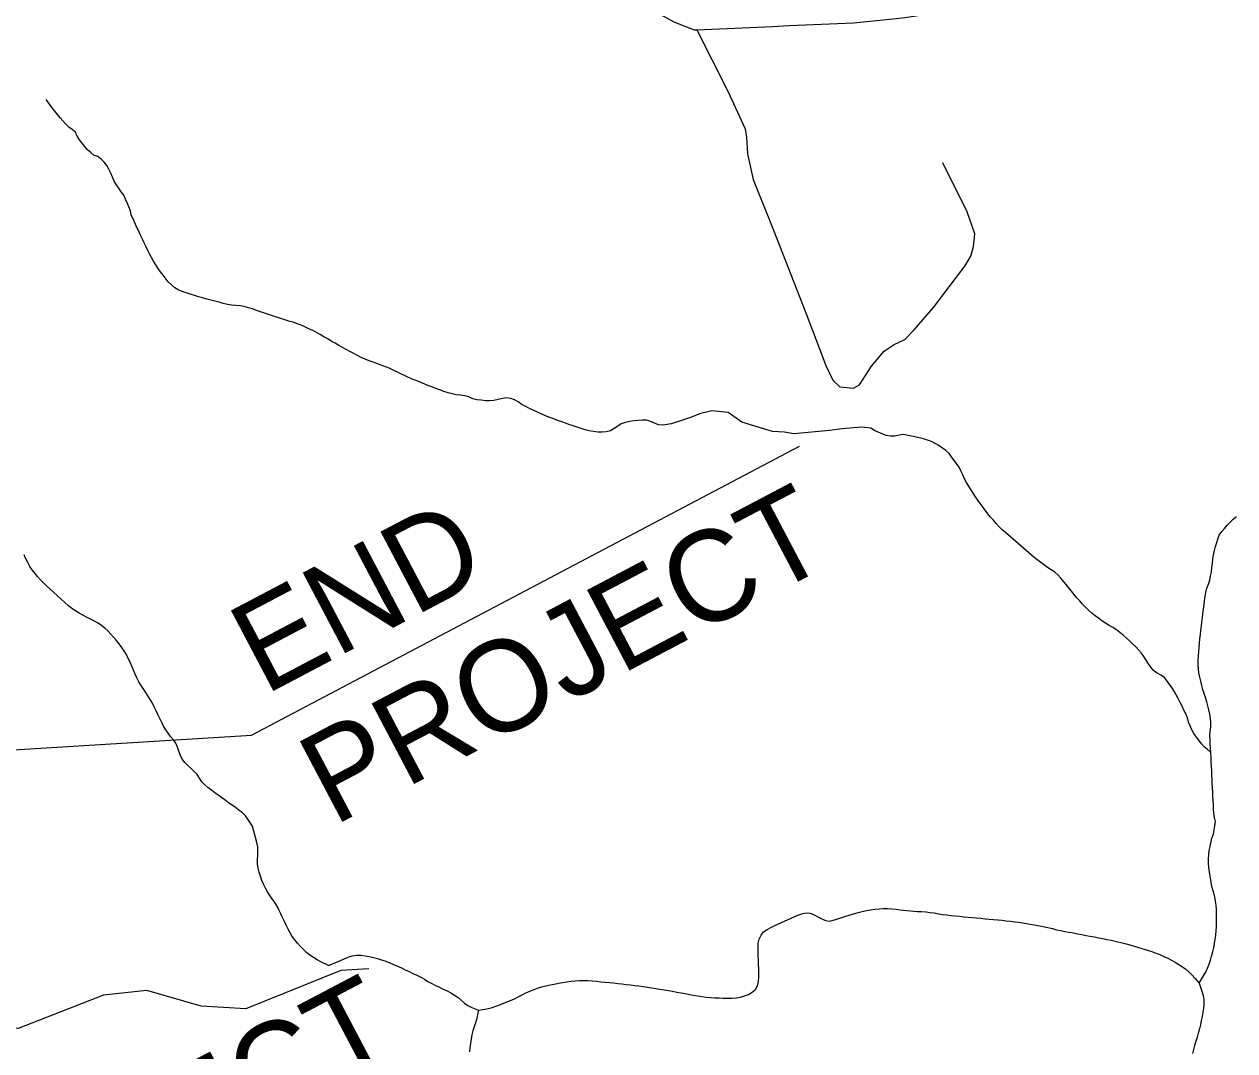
# Model space of a CAD drawing. Extents: x 1379448 to 1382868, y 593769 to 596827.
# Drawn here: x 1379976 to 1380162.2, y 595600.1 to 595758 of the extents above; entities that cross this region are included whole.
import ezdxf

# ---------------------------------------------------------------- set-up
doc = ezdxf.new("R2010")
doc.units = 0
for name, color, linetype in [('Old_Level_11', 7, 'Continuous'), ('Old_Level_32', 7, 'Continuous'), ('Old_Level_35', 7, 'Continuous'), ('Old_Level_59', 7, 'Continuous'), ('Old_Level_62', 7, 'Continuous')]:
    doc.layers.add(name, color=color, linetype=linetype)

msp = doc.modelspace()

# ---------------------------------------------------------------- linework, layer by layer
at = {"layer": 'Old_Level_11'}
for p, q in [((1380010.99, 595648.67), (1380095.29, 595693.12)), ((1379924.01, 595643.23), (1380010.99, 595648.67))]:
    msp.add_line(p, q, dxfattribs=at)
at = {"layer": 'Old_Level_32'}
msp.add_lwpolyline([(1380034.62, 595764.81), (1380038.89, 595766.64), (1380042.27, 595767.47), (1380047.28, 595767.89), (1380058.23, 595765.94), (1380063.55, 595764.52), (1380070.37, 595761.5), (1380075.96, 595758.38), (1380079.07, 595757.17), (1380079.47, 595757.16), (1380091.16, 595757.66), (1380093.69, 595757.86), (1380103.6, 595758.24), (1380110.14, 595758.91), (1380111.56, 595759.05), (1380126.48, 595761.37), (1380131.43, 595762.22), (1380136.18, 595763.33), (1380139.9, 595764.02), (1380148.64, 595765.89), (1380153.3, 595766.99)], dxfattribs=at)
at = {"layer": 'Old_Level_35'}
msp.add_lwpolyline([(1380079.47, 595757.16), (1380084.28, 595747.74), (1380086.91, 595741.93), (1380087.13, 595740.67), (1380087.29, 595738.11), (1380088.18, 595734.14), (1380091.29, 595726.37), (1380096.26, 595713.65), (1380099.33, 595705.54), (1380100.42, 595703.26), (1380101.51, 595702.24), (1380103.57, 595702.06), (1380104.5, 595702.55), (1380106.36, 595705.44), (1380108.31, 595707.74), (1380109.85, 595708.76), (1380111.51, 595709.53), (1380112.91, 595711.01), (1380115.88, 595714.47), (1380120.71, 595720.83), (1380121.63, 595722.37), (1380122.05, 595723.86), (1380122.25, 595725.77), (1380121.1, 595729.18), (1380117.34, 595736.72)], dxfattribs=at)
at = {"layer": 'Old_Level_59'}
for points in [[(1380029.06, 595612.69), (1380024.72, 595612.43), (1380010.13, 595606.57), (1380003.24, 595606.94), (1379994.91, 595609.37), (1379988.23, 595608.66), (1379975.1, 595603.54), (1379971.47, 595604.07), (1379963.32, 595610.7), (1379954.37, 595613.7), (1379940.34, 595615.62), (1379920.78, 595632.39), (1379911.66, 595641.62), (1379894.65, 595661.43), (1379873.48, 595677.68), (1379868.88, 595686.83), (1379868.53, 595690.48), (1379874.38, 595703.4), (1379871.94, 595708.2), (1379865.99, 595712.11)], [(1380156.77, 595610.51), (1380157.17, 595609.26), (1380157.36, 595608.63), (1380157.5, 595607.99), (1380157.5, 595607.33), (1380157.42, 595606.68), (1380157.33, 595606.03), (1380157.22, 595605.38), (1380157.09, 595604.74), (1380156.95, 595604.09), (1380156.8, 595603.46), (1380156.63, 595602.82), (1380156.44, 595602.19), (1380156.25, 595601.56), (1380156.07, 595600.93), (1380155.9, 595600.3), (1380155.75, 595599.66)]]:
    msp.add_lwpolyline(points, dxfattribs=at)
at = {"layer": 'Old_Level_62'}
for points in [[(1379985.36, 595739.22), (1379984.94, 595739.72), (1379984.54, 595740.25), (1379984.17, 595740.79), (1379983.91, 595741.4), (1379983.43, 595741.83), (1379982.87, 595742.2), (1379982.41, 595742.66), (1379981.97, 595743.15), (1379981.55, 595743.65), (1379981.13, 595744.16), (1379980.72, 595744.67), (1379980.32, 595745.19), (1379979.93, 595745.72), (1379979.42, 595746.45)], [(1380043.15, 595700.95), (1380042.49, 595701.02), (1380041.85, 595701.15), (1380041.22, 595701.33), (1380040.6, 595701.54), (1380039.98, 595701.76), (1380039.36, 595701.99), (1380038.75, 595702.22), (1380038.13, 595702.46), (1380037.53, 595702.7), (1380036.91, 595702.95), (1380036.31, 595703.2), (1380035.7, 595703.45), (1380033.94, 595704.27), (1380032.16, 595705.12), (1380029.7, 595706.03), (1380029.08, 595706.24), (1380028.48, 595706.5), (1380027.88, 595706.77), (1380027.29, 595707.07), (1380026.71, 595707.36), (1380026.13, 595707.67), (1380025.55, 595707.98), (1380024.98, 595708.31), (1380024.41, 595708.63), (1380023.84, 595708.96), (1380023.27, 595709.29), (1380022.71, 595709.62), (1380022.14, 595709.95), (1380021.57, 595710.28), (1380020.99, 595710.59), (1380020.41, 595710.9), (1380019.82, 595711.19), (1380019.22, 595711.46), (1380018.62, 595711.72), (1380018.01, 595711.96), (1380017.39, 595712.18), (1380016.76, 595712.35), (1380013.01, 595713.58), (1380012.4, 595713.8), (1380011.77, 595714.01), (1380011.15, 595714.22), (1380010.52, 595714.41), (1380009.89, 595714.58), (1380009.25, 595714.69), (1380008.59, 595714.75), (1380007.93, 595714.81), (1380007.29, 595714.93), (1380006.65, 595715.09), (1380006.01, 595715.25), (1380005.37, 595715.41), (1380004.73, 595715.57), (1380004.1, 595715.75), (1380003.46, 595715.92), (1380002.83, 595716.1), (1380002.2, 595716.29), (1380001.57, 595716.49), (1380000.95, 595716.69), (1380000.34, 595716.92), (1379999.73, 595717.15), (1379999.18, 595717.48), (1379998.67, 595717.92), (1379998.19, 595718.39), (1379997.42, 595719.41), (1379997.02, 595719.94), (1379996.64, 595720.47), (1379996.27, 595721.02), (1379995.92, 595721.57), (1379995.62, 595722.15), (1379995.31, 595722.73), (1379995.02, 595723.32), (1379994.73, 595723.91), (1379994.44, 595724.5), (1379994.16, 595725.09), (1379993.87, 595725.68), (1379993.6, 595726.28), (1379993.32, 595726.88), (1379993.05, 595727.47), (1379992.77, 595728.07), (1379992.5, 595728.66), (1379992.36, 595729.31), (1379992.13, 595729.92), (1379991.89, 595730.54), (1379991.63, 595731.14), (1379991.33, 595731.72), (1379990.97, 595732.27), (1379990.58, 595732.8), (1379990.21, 595733.34), (1379989.89, 595733.91), (1379989.61, 595734.51), (1379989.34, 595735.12), (1379989.06, 595735.71), (1379988.75, 595736.28), (1379988.35, 595736.8), (1379987.86, 595737.26), (1379987.35, 595737.67), (1379986.77, 595737.85), (1379986.27, 595738.28), (1379985.79, 595738.73), (1379985.36, 595739.22)], [(1380111.24, 595694.91), (1380110.6, 595694.8), (1380109.93, 595694.68), (1380109.27, 595694.65), (1380108.63, 595694.78), (1380108.02, 595695.02), (1380107.41, 595695.27), (1380106.82, 595695.55), (1380106.26, 595695.89), (1380104.85, 595696.06), (1380103.61, 595695.93), (1380101.86, 595695.79), (1380099.9, 595695.54), (1380094.42, 595695.01), (1380092.97, 595695.29), (1380091.11, 595695.35), (1380088.92, 595696.03), (1380086.42, 595696.81), (1380084.31, 595698.32), (1380081.82, 595698.57), (1380079.89, 595698.09), (1380079.29, 595697.83), (1380078.68, 595697.59), (1380078.06, 595697.37), (1380077.44, 595697.15), (1380076.82, 595696.94), (1380076.19, 595696.74), (1380075.56, 595696.57), (1380074.91, 595696.43), (1380074.25, 595696.36), (1380073.61, 595696.41), (1380072.99, 595696.64), (1380072.37, 595696.92), (1380071.75, 595697.1), (1380071.1, 595697.12), (1380070.44, 595697.09), (1380069.78, 595697.02), (1380069.12, 595696.91), (1380068.48, 595696.76), (1380067.88, 595696.54), (1380067.32, 595696.19), (1380066.77, 595695.82), (1380066.19, 595695.5), (1380065.56, 595695.3), (1380064.91, 595695.25), (1380064.25, 595695.29), (1380063.6, 595695.35), (1380062.95, 595695.47), (1380062.32, 595695.65), (1380061.7, 595695.85), (1380061.07, 595696.05), (1380060.45, 595696.26), (1380059.82, 595696.47), (1380059.21, 595696.69), (1380058.59, 595696.91), (1380057.97, 595697.13), (1380057.35, 595697.36), (1380056.74, 595697.6), (1380056.14, 595697.86), (1380053.77, 595698.9), (1380053.18, 595699.2), (1380052.6, 595699.55), (1380052.03, 595699.92), (1380051.46, 595700.23), (1380050.87, 595700.46), (1380050.24, 595700.53), (1380049.6, 595700.46), (1380048.94, 595700.3), (1380048.28, 595700.15), (1380047.62, 595700.08), (1380046.97, 595700.1), (1380046.31, 595700.17), (1380045.66, 595700.27), (1380045.02, 595700.4), (1380044.42, 595700.69), (1380043.8, 595700.88), (1380043.15, 595700.95)], [(1380158.55, 595646), (1380158.06, 595646.43), (1380157.56, 595646.86), (1380157.1, 595647.33), (1380155.96, 595648.9), (1380155.65, 595649.49), (1380155.37, 595650.08), (1380155.11, 595650.68), (1380154.96, 595651.32), (1380154.69, 595651.92), (1380154.41, 595652.51), (1380154.13, 595653.1), (1380153.83, 595653.69), (1380153.54, 595654.28), (1380153.23, 595654.86), (1380152.92, 595655.43), (1380152.55, 595655.98), (1380151.42, 595657.54), (1380150.87, 595657.89), (1380150.29, 595658.21), (1380149.76, 595658.6), (1380149.35, 595659.1), (1380148.98, 595659.65), (1380148.63, 595660.21), (1380148.27, 595660.77), (1380147.88, 595661.29), (1380147.45, 595661.79), (1380147, 595662.26), (1380146.53, 595662.72), (1380146.05, 595663.17), (1380145.56, 595663.61), (1380145.06, 595664.04), (1380144.55, 595664.45), (1380144.03, 595664.85), (1380143.5, 595665.24), (1380142.92, 595665.55), (1380142.35, 595665.87), (1380141.81, 595666.25), (1380141.28, 595666.64), (1380140.76, 595667.04), (1380140.25, 595667.45), (1380139.75, 595667.88), (1380139.27, 595668.33), (1380138.82, 595668.8), (1380138.39, 595669.3), (1380137.97, 595669.8), (1380137.56, 595670.32), (1380136.32, 595671.82), (1380135.47, 595672.82), (1380135.05, 595673.32), (1380134.55, 595673.74), (1380134.01, 595674.11), (1380133.45, 595674.47), (1380131.37, 595676), (1380126.95, 595679.82), (1380126.47, 595680.27), (1380126.01, 595680.73), (1380125.56, 595681.22), (1380125.12, 595681.71), (1380124.69, 595682.21), (1380124.28, 595682.71), (1380122.74, 595684.79), (1380122.38, 595685.33), (1380120.98, 595687.53), (1380120.69, 595688.11), (1380120.41, 595688.71), (1380120.12, 595689.31), (1380119.83, 595689.89), (1380118.69, 595691.48), (1380118.29, 595692), (1380117.81, 595692.43), (1380117.29, 595692.83), (1380116.73, 595693.21), (1380116.16, 595693.54), (1380115.58, 595693.82), (1380114.97, 595694.06), (1380114.34, 595694.25), (1380113.7, 595694.41), (1380113.05, 595694.56), (1380111.24, 595694.91)], [(1380158.55, 595646), (1380158.48, 595647.31), (1380158.44, 595647.96), (1380158.42, 595648.62), (1380158.46, 595649.27), (1380158.55, 595649.93), (1380158.57, 595650.58), (1380158.49, 595651.23), (1380158.39, 595651.88), (1380158.26, 595652.53), (1380158.12, 595653.17), (1380157.95, 595653.8), (1380157.76, 595654.43), (1380157.55, 595655.05), (1380157.35, 595655.68), (1380157.18, 595656.31), (1380157.01, 595656.95), (1380156.85, 595657.59), (1380156.73, 595658.23), (1380156.66, 595658.88), (1380156.62, 595659.54), (1380156.62, 595660.19), (1380156.64, 595660.85), (1380156.69, 595661.51), (1380156.75, 595662.16), (1380156.81, 595662.81), (1380156.88, 595663.47), (1380156.95, 595664.12), (1380157.02, 595664.78), (1380157.1, 595665.43), (1380157.18, 595666.08), (1380157.26, 595666.73), (1380157.34, 595667.38), (1380157.42, 595668.03), (1380157.52, 595668.69), (1380157.6, 595669.33), (1380157.7, 595669.98), (1380157.8, 595670.63), (1380157.96, 595671.27), (1380158.19, 595671.89), (1380158.4, 595672.51), (1380158.53, 595673.15), (1380158.64, 595673.8), (1380158.73, 595674.45), (1380158.81, 595675.1), (1380158.89, 595675.75), (1380158.99, 595676.4), (1380159.1, 595677.05), (1380159.26, 595677.68), (1380159.82, 595679.44), (1380160.23, 595679.97), (1380160.65, 595680.47), (1380161.09, 595680.96), (1380161.55, 595681.43), (1380162.02, 595681.88), (1380162.53, 595682.31)], [(1379982.84, 595668.53), (1379979.47, 595671.64), (1379979, 595672.1), (1379978.54, 595672.57), (1379978.1, 595673.06), (1379977.67, 595673.56), (1379977.27, 595674.08), (1379976.91, 595674.63), (1379976.59, 595675.2), (1379976.28, 595675.78), (1379976, 595676.38)], [(1380022.84, 595613.24), (1380021.65, 595613.81), (1380021.07, 595614.1), (1380020.51, 595614.44), (1380019.96, 595614.81), (1380019.45, 595615.22), (1380018.98, 595615.68), (1380018.52, 595616.15), (1380018.08, 595616.64), (1380017.66, 595617.15), (1380017.27, 595617.68), (1380016.93, 595618.23), (1380016.62, 595618.81), (1380016.32, 595619.4), (1380016.05, 595619.99), (1380015.78, 595620.59), (1380015.51, 595621.19), (1380015.22, 595621.79), (1380014.92, 595622.37), (1380014.58, 595622.93), (1380014.19, 595623.46), (1380013.79, 595623.99), (1380013.43, 595624.53), (1380013.13, 595625.12), (1380012.85, 595625.71), (1380012.59, 595626.32), (1380012.37, 595626.95), (1380012.17, 595627.57), (1380012.02, 595628.21), (1380011.94, 595628.85), (1380011.94, 595629.51), (1380011.97, 595630.17), (1380011.99, 595630.83), (1380011.97, 595631.49), (1380011.82, 595632.12), (1380011.14, 595634.65), (1380010.45, 595635.72), (1380010.06, 595636.25), (1380009.59, 595636.71), (1380009.07, 595637.11), (1380008.55, 595637.51), (1380008.01, 595637.89), (1380007.48, 595638.27), (1380006.94, 595638.65), (1380006.41, 595639.03), (1380005.87, 595639.42), (1380005.34, 595639.8), (1380004.82, 595640.19), (1380004.3, 595640.6), (1380003.79, 595641.01), (1380003.37, 595641.5), (1380003, 595642.06), (1380002.62, 595642.59), (1380002.17, 595643.07), (1380001.69, 595643.53), (1380001.2, 595643.98), (1380000.75, 595644.45), (1380000.35, 595644.96), (1380000.05, 595645.54), (1379999.84, 595646.17), (1379999.63, 595646.8), (1379999.37, 595647.4), (1379998.99, 595647.93), (1379998.55, 595648.43), (1379997.8, 595649.48), (1379997.47, 595650.04), (1379997.18, 595650.62), (1379996.89, 595651.22), (1379996.61, 595651.81), (1379996.32, 595652.4), (1379996.03, 595652.99), (1379995.74, 595653.58), (1379994.74, 595655.24), (1379994.01, 595656.32), (1379993.67, 595656.88), (1379993.37, 595657.46), (1379993.08, 595658.05), (1379992.82, 595658.66), (1379992.57, 595659.27), (1379992.31, 595659.87), (1379992.04, 595660.47), (1379991.74, 595661.05), (1379991.41, 595661.62), (1379991.05, 595662.16), (1379990.66, 595662.69), (1379990.24, 595663.21), (1379989.82, 595663.7), (1379989.38, 595664.19), (1379988.92, 595664.67), (1379988.44, 595665.12), (1379987.93, 595665.53), (1379987.39, 595665.89), (1379986.82, 595666.21), (1379986.23, 595666.51), (1379985.63, 595666.8), (1379985.05, 595667.11), (1379984.48, 595667.44), (1379983.92, 595667.78), (1379983.37, 595668.13), (1379982.84, 595668.53)], [(1380156.77, 595610.51), (1380157.45, 595611.64), (1380157.78, 595612.21), (1380158.06, 595612.8), (1380158.29, 595613.41), (1380158.49, 595614.04), (1380158.68, 595614.67), (1380158.86, 595615.3), (1380159.01, 595615.94), (1380159.13, 595616.59), (1380159.24, 595617.24), (1380159.33, 595617.89), (1380159.37, 595618.54), (1380159.41, 595619.2), (1380159.43, 595619.86), (1380159.45, 595620.51), (1380159.45, 595621.17), (1380159.43, 595621.83), (1380159.38, 595622.48), (1380159.3, 595623.13), (1380159.16, 595623.77), (1380159.01, 595624.41), (1380158.84, 595625.04), (1380158.68, 595625.68), (1380158.55, 595626.33), (1380158.44, 595626.98), (1380158.34, 595627.63), (1380158.25, 595628.28), (1380158.2, 595628.94), (1380158.19, 595629.59), (1380158.23, 595630.24), (1380158.32, 595630.89), (1380158.45, 595631.54), (1380158.72, 595632.83), (1380158.95, 595633.43), (1380159.09, 595634.07), (1380159.2, 595634.72), (1380159.29, 595635.36), (1380159.1, 595635.98), (1380159.03, 595636.64), (1380158.99, 595637.3), (1380158.96, 595637.95), (1380158.92, 595638.6), (1380158.89, 595639.26), (1380158.85, 595639.91), (1380158.82, 595640.57), (1380158.79, 595641.23), (1380158.76, 595641.88), (1380158.72, 595642.54), (1380158.69, 595643.2), (1380158.66, 595643.85), (1380158.63, 595644.5), (1380158.6, 595645.16), (1380158.55, 595646)], [(1380045.9, 595606.33), (1380046.56, 595606.45), (1380047.2, 595606.56), (1380047.84, 595606.7), (1380049.06, 595607.11), (1380051.45, 595608.11), (1380052.03, 595608.41), (1380052.62, 595608.72), (1380053.21, 595609), (1380055.01, 595609.73), (1380055.63, 595609.92), (1380056.27, 595610.08), (1380056.91, 595610.23), (1380057.55, 595610.36), (1380058.2, 595610.48), (1380058.84, 595610.6), (1380059.49, 595610.72), (1380060.14, 595610.81), (1380060.8, 595610.88), (1380061.45, 595610.92), (1380062.1, 595610.93), (1380062.76, 595610.91), (1380063.42, 595610.86), (1380064.07, 595610.8), (1380064.72, 595610.73), (1380065.37, 595610.67), (1380066.03, 595610.6), (1380066.68, 595610.53), (1380067.34, 595610.45), (1380067.98, 595610.38), (1380068.64, 595610.3), (1380069.29, 595610.23), (1380069.94, 595610.15), (1380070.59, 595610.07), (1380071.24, 595609.99), (1380074.48, 595609.47), (1380075.12, 595609.36), (1380075.77, 595609.25), (1380076.42, 595609.13), (1380077.06, 595609.01), (1380077.71, 595608.89), (1380078.36, 595608.77), (1380079, 595608.66), (1380079.65, 595608.55), (1380080.29, 595608.45), (1380080.95, 595608.37), (1380081.6, 595608.31), (1380082.26, 595608.27), (1380082.92, 595608.24), (1380083.57, 595608.22), (1380084.23, 595608.21), (1380084.88, 595608.22), (1380085.54, 595608.23), (1380086.19, 595608.35), (1380086.81, 595608.55), (1380087.44, 595608.77), (1380088, 595609.1), (1380088.5, 595609.54), (1380088.84, 595610.09), (1380089, 595610.74), (1380089.03, 595611.4), (1380089.03, 595612.05), (1380089.02, 595612.71), (1380089, 595613.37), (1380088.97, 595614.03), (1380088.94, 595614.68), (1380088.93, 595615.34), (1380088.92, 595615.99), (1380088.95, 595616.65), (1380089.1, 595617.28), (1380089.37, 595617.89), (1380089.76, 595618.42), (1380090.31, 595618.77), (1380090.89, 595619.07), (1380091.48, 595619.36), (1380095.05, 595620.94), (1380095.65, 595621.19), (1380096.3, 595621.32), (1380096.94, 595621.28), (1380097.54, 595621), (1380098.13, 595620.71), (1380098.71, 595620.41), (1380099.3, 595620.13), (1380099.95, 595620.03), (1380101.18, 595620.39), (1380102.41, 595620.82), (1380104.29, 595621.38), (1380104.92, 595621.54), (1380105.57, 595621.69), (1380106.21, 595621.79), (1380106.86, 595621.89), (1380107.52, 595621.96), (1380108.17, 595622), (1380108.83, 595621.99), (1380109.48, 595621.94), (1380110.14, 595621.87), (1380110.79, 595621.78), (1380113.4, 595621.55), (1380114.06, 595621.53), (1380114.71, 595621.47)], [(1380114.71, 595621.47), (1380115.37, 595621.39), (1380116.01, 595621.31), (1380116.66, 595621.19), (1380117.29, 595621.06), (1380117.95, 595620.99), (1380118.6, 595620.93), (1380119.25, 595620.86), (1380119.91, 595620.8), (1380120.56, 595620.73), (1380121.21, 595620.67), (1380121.87, 595620.61), (1380122.52, 595620.54), (1380123.17, 595620.48), (1380123.83, 595620.42), (1380124.48, 595620.36), (1380125.14, 595620.3), (1380125.79, 595620.23), (1380126.44, 595620.17), (1380127.09, 595620.1), (1380127.75, 595620.03), (1380128.4, 595619.96), (1380129.05, 595619.88), (1380132.28, 595619.31), (1380134.2, 595618.9), (1380134.84, 595618.73), (1380135.48, 595618.6), (1380136.12, 595618.47), (1380136.77, 595618.35), (1380137.41, 595618.23), (1380138.06, 595618.11), (1380138.7, 595617.99), (1380139.35, 595617.86), (1380139.99, 595617.74), (1380140.64, 595617.62), (1380141.28, 595617.49), (1380141.93, 595617.37), (1380142.57, 595617.24), (1380143.21, 595617.1), (1380145.75, 595616.48), (1380149.5, 595615.35), (1380150.12, 595615.14), (1380150.74, 595614.9), (1380151.34, 595614.63), (1380151.92, 595614.33), (1380152.51, 595614.03), (1380153.08, 595613.71), (1380153.65, 595613.38), (1380154.2, 595613.03), (1380154.74, 595612.64), (1380155.23, 595612.22), (1380155.69, 595611.75), (1380156.12, 595611.25), (1380156.77, 595610.51)], [(1380022.84, 595613.24), (1380023.45, 595613.49), (1380024.06, 595613.74), (1380024.66, 595614), (1380025.27, 595614.25), (1380025.88, 595614.49), (1380026.5, 595614.69), (1380027.15, 595614.8), (1380027.81, 595614.79)], [(1380027.81, 595614.79), (1380028.46, 595614.71), (1380029.11, 595614.6), (1380029.75, 595614.45), (1380030.38, 595614.29), (1380031.01, 595614.1), (1380031.64, 595613.89), (1380032.25, 595613.64), (1380032.85, 595613.38), (1380033.45, 595613.11), (1380034.05, 595612.85), (1380034.64, 595612.57), (1380035.24, 595612.29), (1380035.83, 595612.01), (1380036.42, 595611.73), (1380037.02, 595611.44), (1380037.59, 595611.14), (1380038.12, 595610.74), (1380038.71, 595610.44), (1380039.29, 595610.16), (1380039.89, 595609.87), (1380040.48, 595609.59), (1380041.07, 595609.3), (1380041.65, 595609), (1380042.23, 595608.68), (1380042.77, 595608.31), (1380043.26, 595607.88), (1380043.76, 595607.44), (1380044.28, 595607.05), (1380044.86, 595606.75), (1380045.9, 595606.33)], [(1380045.9, 595606.33), (1380045.78, 595605.69), (1380045.65, 595605.05), (1380045.45, 595604.42), (1380045.22, 595603.8), (1380045.04, 595603.17), (1380044.89, 595602.53), (1380044.76, 595601.89), (1380044.66, 595601.24), (1380044.59, 595600.59), (1380044.55, 595599.93)]]:
    msp.add_lwpolyline(points, dxfattribs=at)

# ---------------------------------------------------------------- texts
at = {"layer": 'Old_Level_11'}
for s, p in [('PROJECT', (1380023.61, 595634.6)), ('END', (1380013, 595654.73)), ('BEGIN PROJECT', (1379900.85, 595529.45))]:
    msp.add_text(s, height=14, rotation=27.7977, dxfattribs=at).set_placement(p)

doc.saveas('drawing.dxf')
